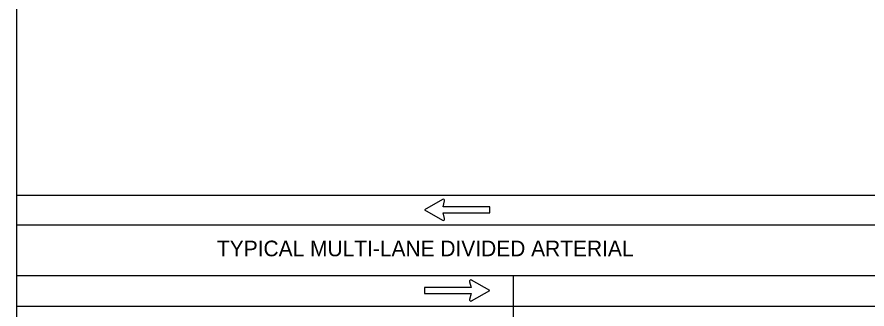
# Model space of a CAD drawing. Extents: x -830008.4 to -829992.7, y 1290284.1 to 1290294.4.
# Drawn here: x -830007.474 to -830003.674, y 1290289.508 to 1290290.815 of the extents above; entities that cross this region are included whole.
import ezdxf

# ---------------------------------------------------------------- set-up
doc = ezdxf.new("R2010")
doc.units = 0
for name, color, linetype in [('1', 7, 'Continuous'), ('LaneDirArrow', 7, 'Continuous'), ('OOCEA Logo', 7, 'Continuous'), ('SheetLines_dp', 7, 'Continuous')]:
    doc.layers.add(name, color=color, linetype=linetype)

msp = doc.modelspace()

# ---------------------------------------------------------------- linework, layer by layer
at = {"layer": '1'}
for p, q in [((-830001.7147, 1290290.0166), (-830007.4742, 1290290.0166)), ((-830001.5198, 1290289.8838), (-830007.4742, 1290289.8838)), ((-830007.4742, 1290289.6579), (-830003.5393, 1290289.6579)), ((-830007.4742, 1290289.5202), (-830003.5393, 1290289.5202))]:
    msp.add_line(p, q, dxfattribs=at)
at = {"layer": 'LaneDirArrow'}
for p, q in [((-830005.5718, 1290289.9986), (-830005.6526, 1290289.952)), ((-830005.5695, 1290289.9659), (-830005.5627, 1290289.9916)), ((-830005.6526, 1290289.952), (-830005.5718, 1290289.9054)), ((-830005.3609, 1290289.9659), (-830005.5695, 1290289.9659)), ((-830005.3609, 1290289.9381), (-830005.3609, 1290289.9659)), ((-830005.5695, 1290289.9381), (-830005.3609, 1290289.9381)), ((-830005.5627, 1290289.9124), (-830005.5695, 1290289.9381)), ((-830005.3609, 1290289.5905), (-830005.4417, 1290289.6372)), ((-830005.4439, 1290289.6044), (-830005.6526, 1290289.6044)), ((-830005.6526, 1290289.6044), (-830005.6526, 1290289.5767)), ((-830005.4508, 1290289.6301), (-830005.4439, 1290289.6044)), ((-830005.6526, 1290289.5767), (-830005.4439, 1290289.5767)), ((-830005.4439, 1290289.5767), (-830005.4508, 1290289.551)), ((-830005.4417, 1290289.5439), (-830005.3609, 1290289.5905))]:
    msp.add_line(p, q, dxfattribs=at)
for centre, start, end in [((-830005.5687, 1290289.9932), 345, 120), ((-830005.5687, 1290289.9108), 240, 15), ((-830005.4448, 1290289.6318), 60, 195), ((-830005.4448, 1290289.5493), 165, 300)]:
    msp.add_arc(centre, 0.00625, start, end, dxfattribs=at)
at = {"layer": 'OOCEA Logo'}
msp.add_line((-830005.2541, 1290289.3045), (-830005.2541, 1290289.6579), dxfattribs=at)
at = {"layer": 'SheetLines_dp'}
msp.add_lwpolyline([(-830007.4742, 1290294.228), (-829992.7742, 1290294.228), (-829992.7742, 1290285.328), (-830007.4742, 1290285.328)], close=True, dxfattribs=at)

# ---------------------------------------------------------------- texts
at = {"layer": '1'}
msp.add_text('TYPICAL MULTI-LANE DIVIDED ARTERIAL', height=0.07, rotation=0.0044, dxfattribs=at).set_placement((-830006.5802, 1290289.7439))

doc.saveas('drawing.dxf')
